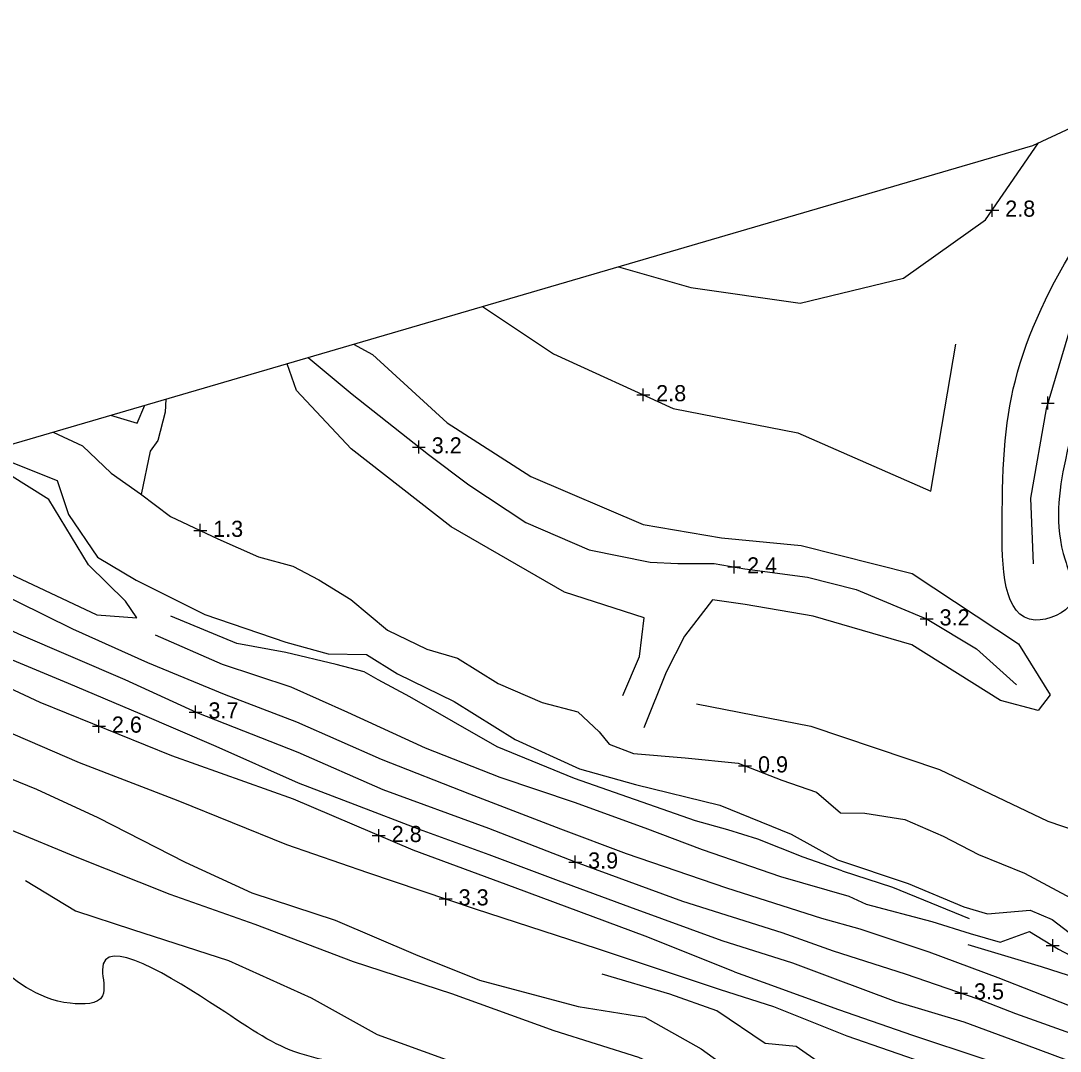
# Model space of a CAD drawing. Extents: x 2316231 to 2323598, y 363169 to 371906.
# Drawn here: x 2322096.8 to 2322418.9, y 368906.5 to 369225.7 of the extents above; entities that cross this region are included whole.
import ezdxf

# ---------------------------------------------------------------- set-up
doc = ezdxf.new("R2010")
doc.units = 0
for name, color, linetype in [('RD_DTM_BkLn1', 7, 'Continuous'), ('RD_DTM_TinHull', 7, 'Continuous'), ('RD_DTM_Void', 7, 'Continuous'), ('RD_EX_H2O', 7, 'Continuous'), ('RD_EX_Road', 7, 'Continuous')]:
    doc.layers.add(name, color=color, linetype=linetype)

msp = doc.modelspace()

# ---------------------------------------------------------------- linework, layer by layer
at = {"layer": 'RD_DTM_BkLn1'}
for points in [[(2322474.953, 369217.107), (2322470.596, 369208.055), (2322462.18, 369196.666), (2322454.805, 369188.146), (2322451.695, 369183.66), (2322438.067, 369161.319), (2322423.171, 369134.713), (2322414.474, 369105.495), (2322409.648, 369077.783), (2322410.455, 369057.496)], [(2322282.038, 369149.526), (2322304.4, 369143.054), (2322338.276, 369138.279), (2322370.257, 369145.943), (2322395.729, 369164.02), (2322412.16, 369187.882)], [(2322239.919, 369137.209), (2322261.876, 369122.599), (2322298.972, 369105.59), (2322337.54, 369098.097), (2322378.783, 369080.046), (2322386.554, 369125.539)], [(2322199.879, 369125.501), (2322205.812, 369122.345), (2322228.897, 369101.21), (2322254.853, 369084.505), (2322289.64, 369069.642), (2322313.931, 369065.492), (2322338.632, 369063.129), (2322372.985, 369054.457), (2322405.882, 369032.72), (2322415.746, 369016.841), (2322411.988, 369012.05), (2322400.324, 369015.142), (2322372.868, 369032.411), (2322342.338, 369041.263), (2322321.22, 369044.871), (2322311.081, 369046.313), (2322302.451, 369035.045), (2322296.749, 369023.906), (2322289.832, 369006.675)], [(2322185.864, 369121.403), (2322199.514, 369110.088), (2322223.098, 369091.326), (2322235.685, 369082.004), (2322253.314, 369070.258), (2322272.968, 369061.815), (2322291.815, 369057.977), (2322300.375, 369057.541), (2322311.661, 369057.594), (2322321.141, 369055.931), (2322340.549, 369053.33), (2322355.634, 369049.479), (2322377.634, 369040.322), (2322392.909, 369031.118), (2322405.348, 369019.981)], [(2322283.354, 369016.695), (2322288.492, 369028.77), (2322289.998, 369040.736), (2322265.265, 369048.748), (2322230.205, 369068.976), (2322199.204, 369093.084), (2322182.23, 369111.165), (2322179.33, 369119.492)], [(2322124.622, 369103.494), (2322132.908, 369101.103), (2322135.226, 369106.595)], [(2322041.686, 369079.242), (2322071.216, 369065.01), (2322095.19, 369053.554), (2322120.342, 369041.704), (2322132.814, 369040.731), (2322129.314, 369045.946), (2322117.771, 369057.122), (2322105.511, 369077.454), (2322093.338, 369085.101), (2322081.506, 369090.886)], [(2322018.729, 369072.529), (2322065.528, 369050.169), (2322096.067, 369035.798), (2322129.009, 369021.597), (2322151.369, 369011.373), (2322182.645, 368999.098), (2322208.994, 368987.56), (2322241.682, 368975.619), (2322268.566, 368965.127), (2322301.837, 368952.965), (2322332.598, 368943.286)], [(2322317.988, 368931.082), (2322290.285, 368942.142), (2322249.993, 368957.091), (2322218.377, 368968.712), (2322181.283, 368984.587), (2322143.628, 368998.031), (2322102.777, 369014.55), (2322077.101, 369026.523), (2322049.645, 369041.2), (2322035.299, 369047.457), (2322009.576, 369059.575), (2321997.518, 369066.327)], [(2321981.677, 369061.694), (2322004.984, 369048.473), (2322043.473, 369028.358), (2322082.824, 369009.751), (2322114.946, 368995.939), (2322145.508, 368984.112), (2322179.113, 368970.562), (2322204.21, 368961.83), (2322237.632, 368950.539), (2322275.392, 368938.24), (2322313.46, 368925.617)], [(2321967.463, 369057.538), (2321976.532, 369052.016), (2322000.508, 369036.905), (2322027.071, 369023.885), (2322053.091, 369011.645), (2322077.506, 368997.498), (2322101.674, 368987.711), (2322120.738, 368978.855), (2322147.723, 368965.019), (2322168.395, 368955.563), (2322194.174, 368947.04), (2322219.087, 368936.411), (2322238.913, 368928.516), (2322269.461, 368920.368), (2322290.164, 368917.026), (2322307.632, 368907.23)], [(2322302.164, 368898.286), (2322288.33, 368904.467), (2322262.059, 368912.743), (2322230.382, 368924.21), (2322199.874, 368934.149), (2322169.428, 368945.677), (2322143.059, 368955.041), (2322113.82, 368966.7), (2322093.855, 368974.991), (2322071.741, 368979.516), (2322049.451, 368990.897), (2322030.511, 368999.047), (2322011.042, 369008.074), (2321981.997, 369025.25), (2321959.297, 369037.435), (2321935.117, 369048.079)], [(2322351.259, 368962.357), (2322339.223, 368966.551), (2322325.169, 368972.208), (2322315.832, 368975.076), (2322305.872, 368977.818), (2322268.407, 368990.962), (2322244.454, 369000.77), (2322217.401, 369016.315), (2322207.571, 369021.516), (2322203.234, 369023.968), (2322194.548, 369026.256), (2322178.901, 369030.017), (2322163.806, 369032.806), (2322143.328, 369041.233)], [(2322138.498, 369035.448), (2322159.245, 369026.422), (2322180.536, 369019.385), (2322197.997, 369011.547), (2322222.118, 369000.495), (2322245.264, 368991.327), (2322268.245, 368983.654), (2322290.207, 368975.655), (2322307.894, 368968.974), (2322332.146, 368960.572), (2322353.373, 368954.479)], [(2322306.155, 369014.147), (2322341.61, 369007.16), (2322381.462, 368993.744), (2322415.033, 368977.722), (2322437.131, 368970.236), (2322463.42, 368961.23), (2322482.539, 368951.753), (2322511.882, 368937.238), (2322542.747, 368925.731)], [(2322351.259, 368962.357), (2322366.923, 368957.267), (2322390.668, 368947.568)], [(2322098.288, 368959.374), (2322113.729, 368949.983), (2322131.399, 368944.223), (2322161.19, 368934.561), (2322186.767, 368923.023), (2322207.203, 368911.6), (2322228.599, 368903.917), (2322249.726, 368897.045), (2322275.209, 368886.084), (2322291.066, 368879.069), (2322314.924, 368867.217), (2322335.698, 368860.252), (2322354.053, 368849.503), (2322378.977, 368834.543), (2322411.75, 368821.217), (2322425.158, 368820.323)], [(2322353.373, 368954.479), (2322358.785, 368952.047), (2322379.126, 368946.624), (2322390.93, 368942.968), (2322400.278, 368940.293), (2322409.376, 368943.548), (2322418.366, 368938.132), (2322429.73, 368932.054), (2322439.173, 368930.45), (2322444.419, 368929.935), (2322447.386, 368924.954), (2322435.6, 368925.421), (2322413.074, 368932.637), (2322390.336, 368939.476)], [(2322332.598, 368943.286), (2322348.55, 368937.549), (2322370.77, 368930.429), (2322393.295, 368922.743), (2322405.038, 368918.158), (2322424.894, 368910.995)], [(2322307.632, 368907.23), (2322315.725, 368901.34), (2322327.115, 368896.251), (2322344.947, 368895.349), (2322344.63, 368902.701), (2322337.017, 368907.938), (2322327.49, 368908.837), (2322312.451, 368919.015), (2322297.861, 368924.11), (2322276.91, 368930.382)], [(2322317.988, 368931.082), (2322326.806, 368927.847), (2322350.2, 368919.407), (2322373.136, 368911.439), (2322394.897, 368904.178), (2322414.153, 368897.286), (2322437.571, 368888.846)], [(2322313.46, 368925.617), (2322330.063, 368920.278), (2322352.726, 368911.216), (2322378.978, 368902.182), (2322405.608, 368894.407), (2322433.914, 368883.194), (2322459.4, 368873.068), (2322476.408, 368865.381), (2322501.103, 368854.644), (2322526.49, 368841.79), (2322540.119, 368832.426), (2322548.609, 368824.012), (2322564.803, 368815.114), (2322581.926, 368806.026), (2322590.982, 368805.222), (2322598.664, 368798.48), (2322592.139, 368794.257), (2322581.967, 368802.615), (2322587.87, 368801.605), (2322594.57, 368798.405)]]:
    msp.add_lwpolyline(points, dxfattribs=at)
at = {"layer": 'RD_DTM_TinHull'}
msp.add_lwpolyline([(2319782.271, 371232.132), (2319735.05, 371773.026), (2320925.274, 371905.831), (2321343.399, 371858.015), (2321109.741, 371125.092), (2321259.088, 370783.878), (2321451.866, 370308.131), (2321545.882, 369878.312), (2321496.483, 369600.925), (2321592.742, 369376.322), (2321772.553, 369180.585), (2321930.831, 369046.826), (2322410.389, 369187.058), (2322700.489, 369322.074), (2323031.423, 369488.086), (2323384.71, 369626.658), (2323598.112, 369182.404), (2323506.079, 369141.824), (2322749.057, 368805.183), (2322437.788, 368637.943)], dxfattribs=at)
at = {"layer": 'RD_DTM_Void'}
for p, q in [((2322397.811, 369165.043), (2322397.811, 369169.043)), ((2322395.811, 369167.043), (2322399.811, 369167.043)), ((2322289.676, 369107.852), (2322289.676, 369111.852)), ((2322287.676, 369109.852), (2322291.676, 369109.852)), ((2322413.013, 369107.307), (2322417.013, 369107.307)), ((2322415.013, 369105.307), (2322415.013, 369109.307)), ((2322220.142, 369091.678), (2322220.142, 369095.678)), ((2322218.142, 369093.678), (2322222.142, 369093.678)), ((2322152.421, 369065.835), (2322152.421, 369069.835)), ((2322150.421, 369067.835), (2322154.421, 369067.835)), ((2322315.853, 369056.508), (2322319.853, 369056.508)), ((2322317.853, 369054.508), (2322317.853, 369058.508)), ((2322375.48, 369040.386), (2322379.48, 369040.386)), ((2322377.48, 369038.386), (2322377.48, 369042.386)), ((2322150.962, 369009.559), (2322150.962, 369013.559)), ((2322148.962, 369011.559), (2322152.962, 369011.559)), ((2322119.045, 369007.163), (2322123.045, 369007.163)), ((2322121.045, 369005.163), (2322121.045, 369009.163)), ((2322319.231, 368994.841), (2322323.231, 368994.841)), ((2322321.231, 368992.841), (2322321.231, 368996.841)), ((2322207.738, 368971.266), (2322207.738, 368975.266)), ((2322205.738, 368973.266), (2322209.738, 368973.266)), ((2322268.601, 368963.067), (2322268.601, 368967.067)), ((2322266.601, 368965.067), (2322270.601, 368965.067)), ((2322228.47, 368951.634), (2322228.47, 368955.634)), ((2322226.47, 368953.634), (2322230.47, 368953.634)), ((2322416.546, 368937.229), (2322416.546, 368941.229)), ((2322414.546, 368939.229), (2322418.546, 368939.229)), ((2322386.157, 368924.496), (2322390.157, 368924.496)), ((2322388.157, 368922.496), (2322388.157, 368926.496))]:
    msp.add_line(p, q, dxfattribs=at)
at = {"layer": 'RD_EX_H2O'}
for points in [[(2322141.808, 369108.52), (2322141.539, 369104.524), (2322139.273, 369095.719), (2322136.95, 369092.408), (2322134.07, 369078.994)], [(2322106.828, 369098.291), (2322115.908, 369094.008), (2322124.778, 369085.615), (2322133.903, 369079.119), (2322143.227, 369072.178), (2322157.867, 369065.262), (2322170.499, 369059.677), (2322181.067, 369056.75), (2322189.185, 369052.473), (2322199.067, 369046.447), (2322210.47, 369036.956), (2322222.622, 369031.041), (2322232.163, 369028.207), (2322244.693, 369020.45), (2322258.313, 369014.486), (2322269.395, 369011.638), (2322275.978, 369005.404), (2322279.157, 369001.613), (2322286.69, 368998.714), (2322302.634, 368997.327), (2322319.041, 368995.697), (2322332.632, 368990.438), (2322343.312, 368986.746), (2322350.826, 368980.371), (2322358.337, 368980.196), (2322370.728, 368978.292), (2322382.636, 368973.107), (2322393.548, 368967.395), (2322407.816, 368961.604), (2322424.978, 368952.407)], [(2322086.139, 369092.241), (2322091.246, 369090.052), (2322108.096, 369083.318), (2322111.643, 369072.764), (2322120.552, 369059.569), (2322132.609, 369052.425), (2322153.867, 369041.734), (2322178.906, 369033.182), (2322192.094, 369029.635), (2322203.916, 369029.372), (2322213.584, 369023.444), (2322231.134, 369014.864), (2322250.028, 369003), (2322269.974, 368993.921), (2322287.26, 368989.13), (2322313.393, 368982.718), (2322335.503, 368973.763), (2322349.881, 368965.738), (2322371.778, 368958.42), (2322389.042, 368951.157), (2322396.319, 368948.989), (2322409.539, 368950.147), (2322416.357, 368947.326), (2322425.133, 368940.582)]]:
    msp.add_lwpolyline(points, dxfattribs=at)
for points in [[(2322751.971, 369162.574), (2322733.589, 369146.654), (2322729.771, 369123.459), (2322721.738, 369110.884), (2322701.188, 369106.103), (2322663.144, 369109.446), (2322627.956, 369119.607), (2322603.036, 369125.495), (2322588.66, 369129.841), (2322574.833, 369138.112), (2322564.58, 369119.048), (2322571.588, 369093.832), (2322577.534, 369068.626), (2322568.439, 369041.645), (2322550.719, 369018.445), (2322516.797, 369002.284), (2322488.752, 369001.977), (2322467.402, 369009.063), (2322444.882, 369031.924), (2322435.573, 369065.58), (2322434.302, 369091.318), (2322448.205, 369117.729), (2322470.9, 369141.708), (2322488.268, 369149.863), (2322505.307, 369153.386), (2322522.075, 369144.097), (2322533.024, 369139.854), (2322533.166, 369154.172), (2322503.148, 369183.921), (2322487.439, 369200.557), (2322479.471, 369201.621), (2322467.947, 369186.056), (2322457.416, 369178.46), (2322431.721, 369131.948), (2322420.446, 369089.736), (2322420.366, 369058.684), (2322422.397, 369045.516), (2322411.097, 369040.065), (2322400.859, 369070.064), (2322405.656, 369116.874), (2322427.068, 369161.383), (2322446.388, 369198.96), (2322446.603, 369203.912)], [(2322208.747, 368901.201), (2322183.277, 368905.732), (2322158.063, 368919.923), (2322122.124, 368931.643), (2322122.147, 368923.617), (2322112.165, 368921.307), (2322087.765, 368934.404), (2322057.288, 368956.943), (2322033.541, 368973.676), (2321996.917, 368984.77), (2321973.214, 368994.492), (2321953.822, 369004.127), (2321979.306, 368982.732), (2321993.4, 368969.67), (2321980.55, 368972.438), (2321948.284, 368996.558), (2321912.19, 369022.755), (2321886.426, 369043.496), (2321858.313, 369062.06), (2321841.156, 369069.167), (2321815.393, 369072.996), (2321792.417, 369073.3)], [(2321916.686, 368955.239), (2321923.473, 368951.411), (2321953.602, 368931.228), (2321990.869, 368918.54), (2322022.67, 368904.982), (2322057.091, 368898.483), (2322086.507, 368887.98), (2322115.055, 368881.833), (2322142.054, 368877.395), (2322155.153, 368877.025), (2322177.929, 368870.56), (2322197.809, 368861.983)]]:
    msp.add_spline(points, degree=3, dxfattribs=at)
at = {"layer": 'RD_EX_Road'}
for points in [[(2322032.337, 369076.508), (2322037.321, 369074.192), (2322060.969, 369062.356), (2322086.988, 369050.009), (2322112.838, 369037.354), (2322136.056, 369026.943), (2322159.817, 369017.089), (2322182.288, 369008.501), (2322208.494, 368996.988), (2322235.842, 368986.194), (2322264.049, 368975.391), (2322284.378, 368967.694), (2322315.466, 368957.129), (2322344.928, 368947.689)], [(2322006.713, 369069.015), (2322022.712, 369060.709), (2322047.072, 369048.425), (2322066.039, 369039.415), (2322089.05, 369029.783), (2322111.478, 369020.466), (2322133.703, 369011.116), (2322157.211, 369001.001), (2322182.75, 368989.662), (2322200.364, 368982.897), (2322220.229, 368975.288), (2322241.87, 368967.4), (2322263.306, 368959.382), (2322285.447, 368951.215), (2322314.027, 368940.78), (2322335.964, 368933.82)], [(2322344.928, 368947.689), (2322356.76, 368944.357), (2322378.193, 368937.285), (2322399.482, 368929.273), (2322421.617, 368920.647), (2322437.886, 368914.019), (2322449.639, 368908.128), (2322467.755, 368902.003), (2322482.756, 368896.872), (2322500.977, 368890.029), (2322515.294, 368883.757), (2322531.101, 368875.695), (2322547.074, 368867.633), (2322559.143, 368861.165), (2322577.687, 368850.452), (2322589.946, 368844.913), (2322598.326, 368840.652), (2322620.682, 368830.355), (2322632.15, 368823.371), (2322644.277, 368816.139), (2322657.688, 368809.552), (2322679.196, 368798.692), (2322696.191, 368790.651), (2322709.264, 368783.803)], [(2322335.964, 368933.82), (2322348.335, 368929.209), (2322367.896, 368921.882), (2322389.047, 368915.528), (2322408.338, 368908.46), (2322425.266, 368902.136)]]:
    msp.add_lwpolyline(points, dxfattribs=at)

# ---------------------------------------------------------------- texts
at = {"layer": 'RD_DTM_Void'}
for s, p in [('2.8', (2322401.811, 369165.043)), ('2.8', (2322293.676, 369107.852)), ('3.2', (2322224.142, 369091.678)), ('1.3', (2322156.421, 369065.835)), ('2.4', (2322321.853, 369054.508)), ('3.2', (2322381.48, 369038.386)), ('3.7', (2322154.962, 369009.559)), ('2.6', (2322125.045, 369005.163)), ('0.9', (2322325.231, 368992.841)), ('2.8', (2322211.738, 368971.266)), ('3.9', (2322272.601, 368963.067)), ('3.3', (2322232.47, 368951.634)), ('3.5', (2322392.157, 368922.496))]:
    msp.add_text(s, height=5, dxfattribs=at).set_placement(p)

doc.saveas('drawing.dxf')
